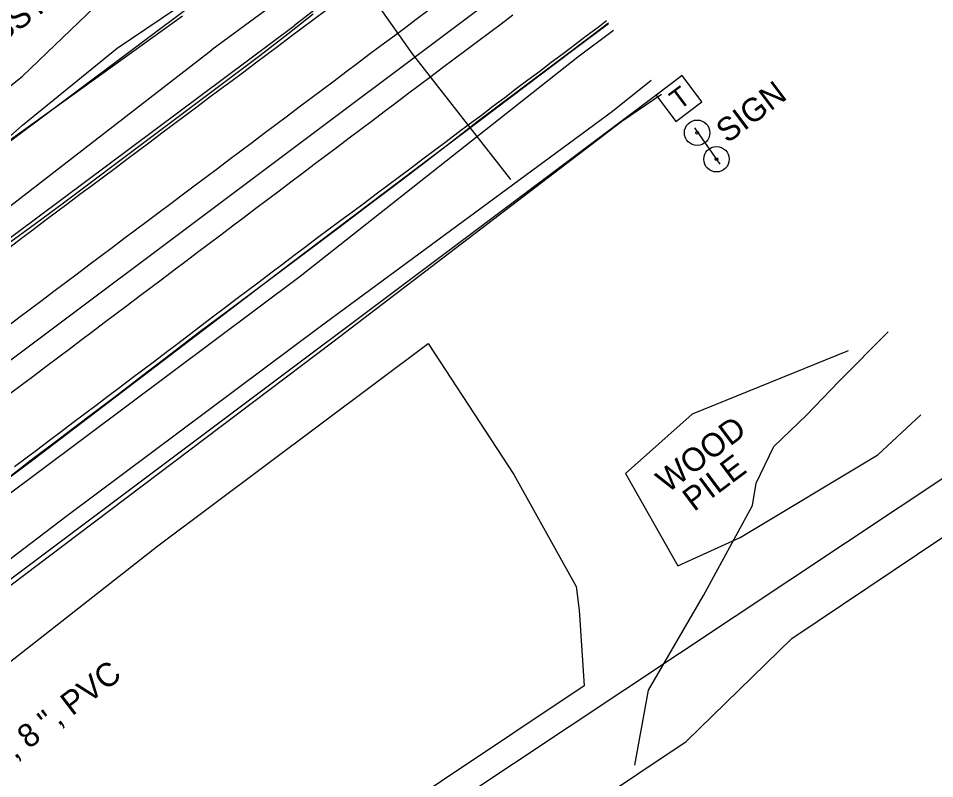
# Model space of a CAD drawing. Extents: x 2186615 to 2188822, y 629899 to 631820.
# Drawn here: x 2188429.1 to 2188585.9, y 631274.6 to 631404.7 of the extents above; entities that cross this region are included whole.
import ezdxf

# ---------------------------------------------------------------- set-up
doc = ezdxf.new("R2010")
doc.units = 0
for name, color, linetype in [('Exist Horizontal Alignment', 7, 'Continuous'), ('Exist Other Culture Area Outline', 7, 'Continuous'), ('Exist Other Culture Area Outline Text', 7, 'Continuous'), ('Exist Other Culture Sign', 7, 'Continuous'), ('Exist Other Culture Sign Post CELL', 7, 'Continuous'), ('Exist Other Culture Sign Text', 7, 'Continuous'), ('Exist Right of Way Line', 7, 'Continuous'), ('Exist Roads EOP', 7, 'Continuous'), ('Exist Roads EOP Text', 7, 'Continuous'), ('Exist Roads EOT', 7, 'Continuous'), ('Exist Utilities Gas UG Line SUE LOS B', 7, 'Continuous'), ('Exist Utilities Sanitary Sewer Forced Main SUE LOS B', 7, 'Continuous'), ('Exist Utilities Sanitary Sewer Forced Main SUE LOS B Text', 7, 'Continuous'), ('Exist Utilities Telephone Pedestal CELL', 7, 'Continuous'), ('Exist Utilities Telephone UG Cable SUE LOS C', 7, 'Continuous'), ('Exist Utilities Telephone UG FO SUE LOS B', 7, 'Continuous'), ('Exist Utilities Water UG Line SUE LOS B', 7, 'Continuous'), ('Exist Vegetation Hedge Row', 7, 'Continuous'), ('Exist Vegetation Woods Line', 7, 'Continuous')]:
    doc.layers.add(name, color=color, linetype=linetype)

msp = doc.modelspace()

# ---------------------------------------------------------------- linework, layer by layer
at = {"layer": 'Exist Horizontal Alignment'}
msp.add_line((2187136.41, 630378.11), (2188520.86, 631416.04), dxfattribs=at)
at = {"layer": 'Exist Other Culture Area Outline'}
msp.add_lwpolyline([(2188571.05, 631347.8), (2188544.38, 631336.96), (2188532.99, 631326.77), (2188541.92, 631310.99), (2188552.59, 631315.86), (2188576.12, 631329.98), (2188583.51, 631336.81)], dxfattribs=at)
at = {"layer": 'Exist Other Culture Sign'}
msp.add_line((2188544.77, 631385.92), (2188549.13, 631379.7), dxfattribs=at)
at = {"layer": 'Exist Other Culture Sign Post CELL'}
for centre, radius in [((2188545.23, 631385.09), 2.18), ((2188545.23, 631385.09), 0.24), ((2188548.54, 631380.56), 2.18), ((2188548.54, 631380.56), 0.24)]:
    msp.add_circle(centre, radius, dxfattribs=at)
at = {"layer": 'Exist Right of Way Line'}
for p, q in [((2187118.41, 630402.11), (2188502.83, 631440.02)), ((2187154.4, 630354.1), (2188538.85, 631392.04)), ((2187850.54, 630836.34), (2188624.63, 631350.85))]:
    msp.add_line(p, q, dxfattribs=at)
at = {"layer": 'Exist Roads EOP'}
for points in [[(2188407.73, 631351.93), (2188412.58, 631355.47), (2188417.43, 631359), (2188422.29, 631362.52), (2188427.16, 631366.03), (2188432.02, 631369.54), (2188436.84, 631373.11), (2188441.63, 631376.72), (2188446.43, 631380.33), (2188451.22, 631383.93), (2188456.02, 631387.53), (2188460.83, 631391.12), (2188465.64, 631394.71), (2188470.43, 631398.33), (2188475.18, 631402), (2188479.55, 631405.46)], [(2188530.04, 631403.82), (2188526.96, 631401.49), (2188522.16, 631397.88), (2188517.37, 631394.27), (2188512.58, 631390.66), (2188507.79, 631387.05), (2188503.03, 631383.39), (2188498.28, 631379.73), (2188493.51, 631376.08), (2188488.73, 631372.46), (2188483.95, 631368.84), (2188479.15, 631365.24), (2188474.35, 631361.64), (2188469.54, 631358.04), (2188464.74, 631354.45), (2188459.94, 631350.85), (2188455.16, 631347.22), (2188450.41, 631343.56), (2188445.65, 631339.9), (2188440.86, 631336.29), (2188436.07, 631332.68), (2188431.29, 631329.05), (2188426.54, 631325.39)]]:
    msp.add_lwpolyline(points, dxfattribs=at)
at = {"layer": 'Exist Roads EOT'}
for points in [[(2188427.18, 631351.96), (2188429.17, 631353.46), (2188431.17, 631354.97), (2188433.17, 631356.47), (2188435.17, 631357.97), (2188437.17, 631359.47), (2188439.16, 631360.98), (2188441.16, 631362.48), (2188443.16, 631363.98), (2188445.16, 631365.48), (2188447.16, 631366.98), (2188449.16, 631368.48), (2188451.16, 631369.98), (2188453.16, 631371.49), (2188455.16, 631372.99), (2188457.15, 631374.49), (2188459.15, 631375.99), (2188461.15, 631377.49), (2188463.15, 631378.99), (2188465.15, 631380.49), (2188467.15, 631381.99), (2188469.15, 631383.5), (2188471.15, 631385), (2188473.15, 631386.5), (2188475.15, 631388), (2188477.14, 631389.5), (2188479.14, 631391), (2188481.14, 631392.5), (2188483.14, 631394), (2188485.14, 631395.51), (2188487.14, 631397.01), (2188489.14, 631398.51), (2188491.14, 631400.01), (2188493.14, 631401.51), (2188495.14, 631403.01), (2188497.13, 631404.51), (2188499.13, 631406.01)], [(2188427.65, 631365.53), (2188429.65, 631367.04), (2188431.64, 631368.55), (2188433.64, 631370.05), (2188435.64, 631371.56), (2188437.64, 631373.06), (2188439.64, 631374.56), (2188441.64, 631376.05), (2188443.64, 631377.55), (2188445.64, 631379.05), (2188447.64, 631380.55), (2188449.64, 631382.05), (2188451.64, 631383.55), (2188453.64, 631385.05), (2188455.64, 631386.55), (2188457.64, 631388.05), (2188459.64, 631389.55), (2188461.64, 631391.04), (2188463.64, 631392.54), (2188465.65, 631394.04), (2188467.65, 631395.54), (2188469.65, 631397.04), (2188471.65, 631398.54), (2188473.65, 631400.04), (2188475.65, 631401.54), (2188477.65, 631403.03), (2188479.65, 631404.53), (2188481.65, 631406.03)], [(2188427.82, 631340.57), (2188429.82, 631342.07), (2188431.81, 631343.57), (2188433.81, 631345.08), (2188435.81, 631346.58), (2188437.8, 631348.09), (2188439.8, 631349.59), (2188441.8, 631351.09), (2188443.79, 631352.6), (2188445.79, 631354.1), (2188447.78, 631355.61), (2188449.78, 631357.11), (2188451.78, 631358.62), (2188453.77, 631360.12), (2188455.77, 631361.63), (2188457.77, 631363.13), (2188459.76, 631364.64), (2188461.76, 631366.14), (2188463.75, 631367.65), (2188465.75, 631369.15), (2188467.75, 631370.66), (2188469.74, 631372.16), (2188471.74, 631373.67), (2188473.74, 631375.17), (2188475.73, 631376.68), (2188477.73, 631378.18), (2188479.72, 631379.69), (2188481.72, 631381.19), (2188483.72, 631382.7), (2188485.71, 631384.2), (2188487.71, 631385.71), (2188489.71, 631387.21), (2188491.7, 631388.72), (2188493.7, 631390.22), (2188495.69, 631391.73), (2188497.69, 631393.23), (2188499.69, 631394.74), (2188501.69, 631396.24), (2188503.68, 631397.74), (2188505.68, 631399.24), (2188507.68, 631400.74), (2188509.68, 631402.24), (2188511.68, 631403.74), (2188513.68, 631405.24)], [(2188529.74, 631404.22), (2188528.27, 631403.11), (2188526.27, 631401.61), (2188524.27, 631400.1), (2188522.28, 631398.6), (2188520.28, 631397.09), (2188518.29, 631395.59), (2188516.29, 631394.08), (2188514.29, 631392.58), (2188512.3, 631391.07), (2188510.3, 631389.57), (2188508.31, 631388.06), (2188506.31, 631386.56), (2188504.31, 631385.05), (2188502.31, 631383.55), (2188500.31, 631382.05), (2188498.31, 631380.56), (2188496.31, 631379.06), (2188494.3, 631377.56), (2188492.3, 631376.07), (2188490.3, 631374.57), (2188488.3, 631373.07), (2188486.3, 631371.58), (2188484.29, 631370.08), (2188482.29, 631368.58), (2188480.29, 631367.09), (2188478.29, 631365.58), (2188476.3, 631364.07), (2188474.3, 631362.57), (2188472.31, 631361.06), (2188470.31, 631359.55), (2188468.32, 631358.04), (2188466.33, 631356.54), (2188464.33, 631355.03), (2188462.34, 631353.52), (2188460.34, 631352.01), (2188458.35, 631350.5), (2188456.36, 631349), (2188454.36, 631347.49), (2188452.37, 631345.98), (2188450.37, 631344.47), (2188448.38, 631342.97), (2188446.39, 631341.46), (2188444.39, 631339.95), (2188442.4, 631338.44), (2188440.4, 631336.94), (2188438.4, 631335.44), (2188436.41, 631333.93), (2188434.41, 631332.43), (2188432.41, 631330.92), (2188430.42, 631329.42), (2188428.42, 631327.91)]]:
    msp.add_lwpolyline(points, dxfattribs=at)
at = {"layer": 'Exist Utilities Gas UG Line SUE LOS B'}
msp.add_lwpolyline([(2188417.18, 631375.21), (2188429.81, 631386.38), (2188446.01, 631399.58), (2188455.97, 631406.32), (2188463.22, 631411.89), (2188467.43, 631414.38), (2188472.51, 631417.98), (2188478.88, 631421.23), (2188489.17, 631427.76), (2188497.99, 631434.15), (2188504.03, 631438.42)], dxfattribs=at)
at = {"layer": 'Exist Utilities Sanitary Sewer Forced Main SUE LOS B'}
for points in [[(2188476.69, 631425.88), (2188483.56, 631416.9), (2188496.5, 631398.59), (2188513.28, 631377.11)], [(2188052.08, 631035.89), (2188074.5, 631052.61), (2188093.79, 631066.37), (2188121.43, 631086.62), (2188146.17, 631105.29), (2188183, 631130.32), (2188212.25, 631151.9), (2188236.06, 631169.55), (2188274.9, 631197.79), (2188300.59, 631215.98), (2188344.72, 631249.04), (2188387.13, 631281.33), (2188437.44, 631319.58), (2188480.75, 631351.94), (2188530.77, 631388.8), (2188537.37, 631394.07)]]:
    msp.add_lwpolyline(points, dxfattribs=at)
at = {"layer": 'Exist Utilities Telephone Pedestal CELL'}
msp.add_line((2188542.05, 631390.92), (2188542.05, 631390.92), dxfattribs=at)
msp.add_lwpolyline([(2188541.56, 631387.03), (2188546.04, 631390.38), (2188542.69, 631394.86), (2188538.21, 631391.51), (2188541.56, 631387.03)], dxfattribs=at)
at = {"layer": 'Exist Utilities Telephone UG Cable SUE LOS C'}
for points in [[(2188510.44, 631429.9), (2188476.35, 631403.47)], [(2188359.63, 631339.91), (2188390.14, 631363.91), (2188406.42, 631376.04), (2188429.82, 631394.77), (2188450.5, 631414.66)], [(2188239.88, 631089.23), (2188209.7, 631139.17), (2188205.31, 631145.33), (2188202.92, 631147.6), (2188200.81, 631153.01), (2188202.37, 631156.1), (2188209.69, 631162.82), (2188228.85, 631177.06), (2188268.68, 631206.68), (2188293.54, 631225.66), (2188339.11, 631259.48), (2188381.57, 631291.6), (2188431.82, 631329.3), (2188475.74, 631362.76), (2188523.99, 631399.21), (2188530.06, 631403.8)], [(2188312.37, 631280.51), (2188341.87, 631302.43), (2188368.35, 631323.01), (2188385.25, 631335.41), (2188398.42, 631345.26), (2188424.55, 631364.83), (2188476.35, 631403.47)], [(2188096.88, 630993.34), (2188080.22, 631017.51), (2188064.37, 631042.87), (2188062.98, 631045.24), (2188062.65, 631047.71), (2188067.09, 631054.3), (2188068.63, 631056.84), (2188089.09, 631072.74), (2188116.44, 631092.81), (2188141.03, 631110.94), (2188178.22, 631138.01), (2188229.96, 631175.9), (2188269.4, 631205.59), (2188294.58, 631224.2), (2188340.11, 631258.2), (2188382.72, 631289.85), (2188432.93, 631327.36), (2188477.32, 631360.56), (2188524.82, 631398.08), (2188530.94, 631402.62)], [(2188094.37, 630991.41), (2188096.88, 630993.34), (2188087.79, 631026.43), (2188086.82, 631054.16), (2188087.06, 631058.84), (2188088.93, 631062.35), (2188093.27, 631066.84), (2188121.22, 631086.85), (2188145.88, 631105.9), (2188182.55, 631131.21), (2188212.13, 631152.41), (2188236.63, 631168.55), (2188279.23, 631192.06), (2188292.43, 631201.57), (2188302.49, 631212.36), (2188347.67, 631244.49), (2188388.98, 631278.39), (2188439.32, 631316.4), (2188482.92, 631349.33), (2188532.32, 631387.1), (2188539.16, 631391.7)]]:
    msp.add_lwpolyline(points, dxfattribs=at)
at = {"layer": 'Exist Utilities Telephone UG FO SUE LOS B'}
msp.add_lwpolyline([(2188303.07, 631290.83), (2188335.53, 631314.77), (2188356.73, 631330.39), (2188376.84, 631345.11), (2188395.22, 631359.35), (2188416.54, 631375.89), (2188457.16, 631405.12)], dxfattribs=at)
at = {"layer": 'Exist Utilities Water UG Line SUE LOS B'}
for points in [[(2188506.72, 631432.41), (2188505.72, 631431.65), (2188488.84, 631418.89), (2188462.18, 631399.29)], [(2188311.2, 631281.93), (2188339.94, 631304.52), (2188359.74, 631320.63), (2188366.75, 631325.42), (2188378.12, 631334.45), (2188382.61, 631338.14), (2188396.4, 631348.39), (2188421.73, 631367.94), (2188462.18, 631399.29)]]:
    msp.add_lwpolyline(points, dxfattribs=at)
at = {"layer": 'Exist Vegetation Hedge Row'}
for points in [[(2188554.68, 631321.3), (2188555.31, 631325.14), (2188558.38, 631331.42), (2188563.93, 631336.78), (2188569.48, 631342.51), (2188577.94, 631351.03)], [(2188534.55, 631276.88), (2188536.9, 631289.7), (2188546.3, 631305.89), (2188554.68, 631321.3)]]:
    msp.add_lwpolyline(points, dxfattribs=at)
at = {"layer": 'Exist Vegetation Woods Line'}
for points in [[(2188405.25, 631276.99), (2188452.97, 631314.41), (2188499.21, 631349.02), (2188513.85, 631326.63), (2188524.54, 631307.43), (2188525.07, 631303.42)], [(2188450.68, 631218.94), (2188543.33, 631280.93), (2188561.43, 631298.58), (2188595.95, 631321.7)], [(2188525.07, 631303.42), (2188525.9, 631290.47), (2188440.29, 631233.26)]]:
    msp.add_lwpolyline(points, dxfattribs=at)

# ---------------------------------------------------------------- texts
at = {"layer": 'Exist Other Culture Area Outline Text'}
for s, p in [('WOOD ', (2188540.16, 631323.35)), ('PILE', (2188544.69, 631320.18))]:
    msp.add_text(s, height=4, rotation=36.8593, dxfattribs=at).set_placement(p)
at = {"layer": 'Exist Other Culture Sign Text'}
msp.add_text('SIGN', height=4, rotation=36.8593, dxfattribs=at).set_placement((2188550.4, 631383.18))
at = {"layer": 'Exist Roads EOP Text'}
msp.add_text('BST', height=4, rotation=36.8593, dxfattribs=at).set_placement((2188426.13, 631400.22))
at = {"layer": 'Exist Utilities Sanitary Sewer Forced Main SUE LOS B Text'}
msp.add_text('Johnston County Public Utility, 8 ", PVC', height=4, rotation=37.3672, dxfattribs=at).set_placement((2188372.27, 631234.8))
at = {"layer": 'Exist Utilities Telephone Pedestal CELL'}
msp.add_text('T', height=3.42, rotation=36.773, dxfattribs=at).set_placement((2188542.17, 631388.87))

doc.saveas('drawing.dxf')
